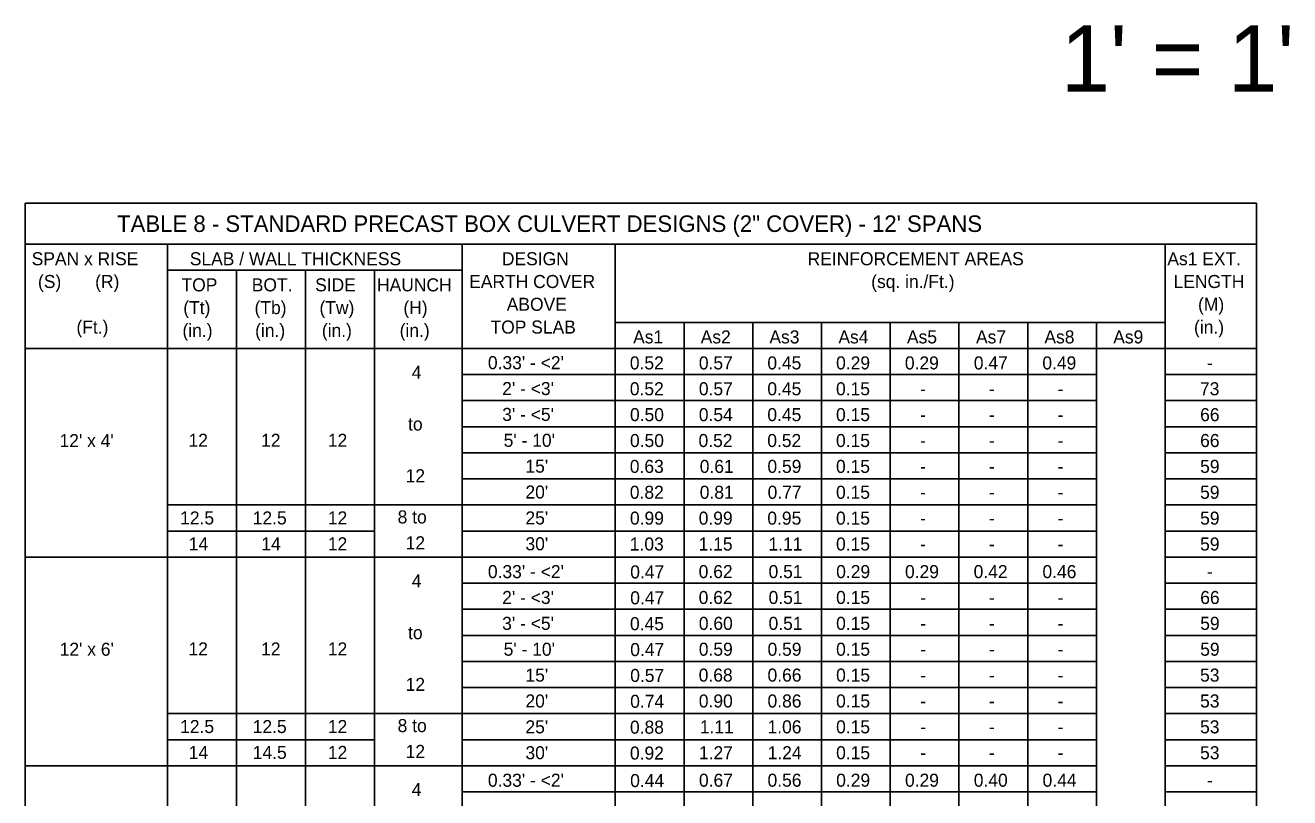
# Model space of a CAD drawing. Extents: x 10351.18 to 10353.4, y 76399.49 to 76400.59.
# Drawn here: x 10351.832 to 10352.443, y 76400.212 to 76400.586 of the extents above; entities that cross this region are included whole.
import ezdxf

# ---------------------------------------------------------------- set-up
doc = ezdxf.new("R2010")
doc.units = 0
doc.layers.add('AdhocPoint_dp', color=7, linetype='Continuous')
doc.layers.add('PlotBorder_dp', color=7, linetype='Continuous')

msp = doc.modelspace()

# ---------------------------------------------------------------- linework, layer by layer
at = {"layer": 'PlotBorder_dp'}
for p, q in [((10351.83244, 76400.49971), (10351.83244, 76399.92549)), ((10351.83244, 76400.49971), (10352.42718, 76400.49971)), ((10352.42718, 76400.49971), (10352.42718, 76399.92549)), ((10351.83244, 76400.47984), (10352.42718, 76400.47984)), ((10351.90108, 76400.47984), (10351.90108, 76399.92549)), ((10352.04352, 76400.47984), (10352.04352, 76399.92549)), ((10352.1174, 76400.47984), (10352.1174, 76399.92549)), ((10352.38299, 76400.47984), (10352.38299, 76399.92549)), ((10351.90108, 76400.46724), (10352.04352, 76400.46724)), ((10351.93444, 76400.46724), (10351.93444, 76399.92549)), ((10351.9678, 76400.46724), (10351.9678, 76399.92549)), ((10352.00116, 76400.46724), (10352.00116, 76399.92549)), ((10352.1174, 76400.44209), (10352.38299, 76400.44209)), ((10352.1506, 76400.44209), (10352.1506, 76399.92549)), ((10352.1838, 76400.44209), (10352.1838, 76399.92549)), ((10352.217, 76400.44209), (10352.217, 76399.92549)), ((10352.2502, 76400.44209), (10352.2502, 76399.92549)), ((10352.28339, 76400.44209), (10352.28339, 76399.92549)), ((10352.28339, 76400.44209), (10352.28339, 76399.92549)), ((10352.31659, 76400.44209), (10352.31659, 76399.92549)), ((10352.34979, 76400.44209), (10352.34979, 76399.92549)), ((10351.83244, 76400.42949), (10352.42718, 76400.42949)), ((10352.04352, 76400.41689), (10352.34979, 76400.41689)), ((10352.38299, 76400.41689), (10352.42718, 76400.41689)), ((10352.04352, 76400.40429), (10352.34979, 76400.40429)), ((10352.38299, 76400.40429), (10352.42718, 76400.40429)), ((10352.04352, 76400.39169), (10352.34979, 76400.39169)), ((10352.38299, 76400.39169), (10352.42718, 76400.39169)), ((10352.04352, 76400.37909), (10352.34979, 76400.37909)), ((10352.38299, 76400.37909), (10352.42718, 76400.37909)), ((10352.04352, 76400.36649), (10352.34979, 76400.36649)), ((10352.38299, 76400.36649), (10352.42718, 76400.36649)), ((10352.04352, 76400.35389), (10351.90108, 76400.35389)), ((10352.04352, 76400.35389), (10352.34979, 76400.35389)), ((10352.38299, 76400.35389), (10352.42718, 76400.35389)), ((10352.00116, 76400.34129), (10351.90108, 76400.34129)), ((10352.04352, 76400.34129), (10352.34979, 76400.34129)), ((10352.38299, 76400.34129), (10352.42718, 76400.34129)), ((10351.83244, 76400.32869), (10352.34979, 76400.32869)), ((10352.04414, 76400.32869), (10352.11631, 76400.32869)), ((10352.38299, 76400.32869), (10352.42718, 76400.32869)), ((10352.04352, 76400.31609), (10352.34979, 76400.31609)), ((10352.38299, 76400.31609), (10352.42718, 76400.31609)), ((10352.04352, 76400.30349), (10352.34979, 76400.30349)), ((10352.38299, 76400.30349), (10352.42718, 76400.30349)), ((10352.04352, 76400.29089), (10352.34979, 76400.29089)), ((10352.38299, 76400.29089), (10352.42718, 76400.29089)), ((10352.04352, 76400.27829), (10352.34979, 76400.27829)), ((10352.38299, 76400.27829), (10352.42718, 76400.27829)), ((10352.04352, 76400.26569), (10352.34979, 76400.26569)), ((10352.38299, 76400.26569), (10352.42718, 76400.26569)), ((10352.04352, 76400.25309), (10351.90108, 76400.25309)), ((10352.04352, 76400.25309), (10352.34979, 76400.25309)), ((10352.38299, 76400.25309), (10352.42718, 76400.25309)), ((10352.00116, 76400.24049), (10351.90108, 76400.24049)), ((10352.04352, 76400.24049), (10352.34979, 76400.24049)), ((10352.04414, 76400.24049), (10352.11631, 76400.24049)), ((10352.38299, 76400.24049), (10352.42718, 76400.24049)), ((10351.83244, 76400.22789), (10352.34979, 76400.22789)), ((10352.38299, 76400.22789), (10352.42718, 76400.22789)), ((10352.04352, 76400.21529), (10352.34979, 76400.21529)), ((10352.38299, 76400.21529), (10352.42718, 76400.21529))]:
    msp.add_line(p, q, dxfattribs=at)

# ---------------------------------------------------------------- texts
at = {"layer": 'AdhocPoint_dp'}
for s, height, p in [("1' = 1'", 0.032, (10352.33259, 76400.55363)), ('TABLE 8 - STANDARD PRECAST BOX CULVERT DESIGNS (2" COVER) - 12\' SPANS', 0.008, (10351.87677, 76400.48578)), ('SLAB / WALL THICKNESS', 0.0063, (10351.9119, 76400.46968)), ('As1', 0.0063, (10352.12602, 76400.43192)), ('As2', 0.0063, (10352.15865, 76400.43192)), ('As3', 0.0063, (10352.19185, 76400.43192)), ('As4', 0.0063, (10352.22517, 76400.43192)), ('As5', 0.0063, (10352.25827, 76400.43192)), ('As7', 0.0063, (10352.29162, 76400.43192)), ('As8', 0.0063, (10352.32466, 76400.43192)), ('As9', 0.0063, (10352.35791, 76400.43192)), ("12' x 4'", 0.0063, (10351.84898, 76400.38182))]:
    msp.add_text(s, height=height, dxfattribs=at).set_placement(p)
at = {"layer": 'PlotBorder_dp'}
for s, p in [('SPAN x RISE', (10351.83553, 76400.46969)), ('DESIGN', (10352.06262, 76400.46969)), ('REINFORCEMENT AREAS', (10352.2103, 76400.46969)), ('(S)       (R)', (10351.83857, 76400.45869)), ('EARTH COVER', (10352.04683, 76400.45869)), ('(sq. in./Ft.)', (10352.241, 76400.45869)), ('TOP', (10351.9079, 76400.45708)), ('BOT.', (10351.94183, 76400.45708)), ('SIDE', (10351.97243, 76400.45708)), ('HAUNCH', (10352.00232, 76400.45708)), ('(Tt)', (10351.90875, 76400.44608)), ('(Tb)', (10351.94317, 76400.44608)), ('(Tw)', (10351.97453, 76400.44608)), ('(H)', (10352.01506, 76400.44608)), ('ABOVE', (10352.06497, 76400.44769)), ('(Ft.)', (10351.85715, 76400.43669)), ('(in.)', (10351.90836, 76400.43508)), ('(in.)', (10351.94345, 76400.43508)), ('(in.)', (10351.97568, 76400.43508)), ('(in.)', (10352.01325, 76400.43508)), ('TOP SLAB', (10352.05714, 76400.43669)), ("0.33' - <2'", (10352.05588, 76400.41948)), ('0.52', (10352.12443, 76400.41937)), ('0.57', (10352.15777, 76400.41937)), ('0.45', (10352.19085, 76400.41937)), ('0.29', (10352.22405, 76400.41937)), ('0.29', (10352.25728, 76400.41937)), ('0.47', (10352.29056, 76400.41937)), ('0.49', (10352.32367, 76400.41937)), ('4', (10352.0191, 76400.41485)), ("2' - <3'", (10352.06278, 76400.40698)), ('0.52', (10352.12443, 76400.40687)), ('0.57', (10352.15777, 76400.40687)), ('0.45', (10352.19085, 76400.40687)), ('0.15', (10352.22401, 76400.40687)), ('-', (10352.26462, 76400.40687)), ('-', (10352.29782, 76400.40687)), ('-', (10352.33101, 76400.40687)), ("3' - <5'", (10352.06278, 76400.39448)), ('0.50', (10352.1245, 76400.39437)), ('0.54', (10352.15775, 76400.39437)), ('0.45', (10352.19085, 76400.39437)), ('0.15', (10352.22401, 76400.39437)), ('-', (10352.26462, 76400.39437)), ('-', (10352.29782, 76400.39437)), ('-', (10352.33101, 76400.39437)), ('to', (10352.01732, 76400.38985)), ('12', (10351.91127, 76400.38198)), ('12', (10351.94634, 76400.38198)), ('12', (10351.97858, 76400.38198)), ("5' - 10'", (10352.06349, 76400.38198)), ('0.50', (10352.1245, 76400.38187)), ('0.52', (10352.15762, 76400.38187)), ('0.52', (10352.19082, 76400.38187)), ('0.15', (10352.22401, 76400.38187)), ('-', (10352.26462, 76400.38187)), ('-', (10352.29782, 76400.38187)), ('-', (10352.33101, 76400.38187)), ("15'", (10352.07401, 76400.36948)), ('0.63', (10352.12442, 76400.36937)), ('0.61', (10352.15819, 76400.36937)), ('0.59', (10352.19089, 76400.36937)), ('0.15', (10352.22401, 76400.36937)), ('12', (10352.01615, 76400.36485)), ('-', (10352.26462, 76400.36937)), ('-', (10352.29782, 76400.36937)), ('-', (10352.33101, 76400.36937)), ("20'", (10352.07401, 76400.35698)), ('0.82', (10352.12443, 76400.35687)), ('0.81', (10352.15819, 76400.35687)), ('0.77', (10352.19097, 76400.35687)), ('0.15', (10352.22401, 76400.35687)), ('-', (10352.26462, 76400.35687)), ('-', (10352.29782, 76400.35687)), ('-', (10352.33101, 76400.35687)), ('12.5', (10351.90723, 76400.34448)), ('12.5', (10351.9423, 76400.34448)), ('12', (10351.97858, 76400.34448)), ('8 to', (10352.01228, 76400.34496)), ("25'", (10352.07401, 76400.34448)), ('0.99', (10352.12449, 76400.34437)), ('0.99', (10352.15769, 76400.34437)), ('0.95', (10352.19085, 76400.34437)), ('0.15', (10352.22401, 76400.34437)), ('-', (10352.26462, 76400.34437)), ('-', (10352.29782, 76400.34437)), ('-', (10352.33101, 76400.34437)), ('14', (10351.9114, 76400.33198)), ('14', (10351.94646, 76400.33198)), ('12', (10351.97858, 76400.33198)), ('12', (10352.01615, 76400.33246)), ("30'", (10352.07401, 76400.33198)), ('1.03', (10352.12442, 76400.33187)), ('1.15', (10352.15765, 76400.33187)), ('1.11', (10352.19139, 76400.33187)), ('0.15', (10352.22401, 76400.33187)), ('-', (10352.26462, 76400.33187)), ('-', (10352.29782, 76400.33187)), ('-', (10352.33101, 76400.33187)), ("0.33' - <2'", (10352.05588, 76400.31854)), ('0.47', (10352.12462, 76400.31838)), ('0.62', (10352.15768, 76400.31854)), ('0.51', (10352.19144, 76400.31854)), ('0.29', (10352.2241, 76400.31854)), ('0.29', (10352.25733, 76400.31854)), ('0.42', (10352.29048, 76400.31854)), ('0.46', (10352.32372, 76400.31854)), ('4', (10352.0191, 76400.31405)), ('-', (10352.40319, 76400.31854)), ("2' - <3'", (10352.06278, 76400.30604)), ('0.47', (10352.12462, 76400.30588)), ('0.62', (10352.15768, 76400.30604)), ('0.51', (10352.19144, 76400.30604)), ('0.15', (10352.22406, 76400.30604)), ('66', (10352.39992, 76400.30604)), ('-', (10352.26467, 76400.30604)), ('-', (10352.29788, 76400.30604)), ('-', (10352.33106, 76400.30604)), ("3' - <5'", (10352.06278, 76400.29354)), ('0.45', (10352.1245, 76400.29338)), ('0.60', (10352.15775, 76400.29354)), ('0.51', (10352.19144, 76400.29354)), ('0.15', (10352.22406, 76400.29354)), ('59', (10352.39992, 76400.29354)), ('to', (10352.01732, 76400.28905)), ('-', (10352.26467, 76400.29354)), ('-', (10352.29788, 76400.29354)), ('-', (10352.33106, 76400.29354)), ("12' x 6'", (10351.84905, 76400.28104)), ('12', (10351.91127, 76400.28118)), ('12', (10351.94634, 76400.28118)), ('12', (10351.97858, 76400.28118)), ("5' - 10'", (10352.06349, 76400.28104)), ('0.47', (10352.12462, 76400.28088)), ('0.59', (10352.15774, 76400.28104)), ('0.59', (10352.19094, 76400.28104)), ('0.15', (10352.22406, 76400.28104)), ('59', (10352.39992, 76400.28104)), ('-', (10352.26467, 76400.28104)), ('-', (10352.29788, 76400.28104)), ('-', (10352.33106, 76400.28104)), ('12', (10352.01615, 76400.26405)), ("15'", (10352.07401, 76400.26854)), ('0.57', (10352.12462, 76400.26838)), ('0.68', (10352.15769, 76400.26854)), ('0.66', (10352.19094, 76400.26854)), ('0.15', (10352.22406, 76400.26854)), ('-', (10352.26467, 76400.26854)), ('-', (10352.29788, 76400.26854)), ('-', (10352.33106, 76400.26854)), ('53', (10352.39985, 76400.26854)), ("20'", (10352.07401, 76400.25604)), ('0.74', (10352.1246, 76400.25588)), ('0.90', (10352.15775, 76400.25604)), ('0.86', (10352.19094, 76400.25604)), ('0.15', (10352.22406, 76400.25604)), ('-', (10352.26467, 76400.25604)), ('-', (10352.29788, 76400.25604)), ('-', (10352.33106, 76400.25604)), ('53', (10352.39985, 76400.25604)), ('8 to', (10352.01228, 76400.24416)), ('12.5', (10351.90723, 76400.24368)), ('12.5', (10351.9423, 76400.24368)), ('12', (10351.97858, 76400.24368)), ("25'", (10352.07401, 76400.24354)), ('0.88', (10352.1245, 76400.24338)), ('1.11', (10352.15824, 76400.24354)), ('1.06', (10352.19094, 76400.24354)), ('0.15', (10352.22406, 76400.24354)), ('-', (10352.26467, 76400.24354)), ('-', (10352.29788, 76400.24354)), ('-', (10352.33106, 76400.24354)), ('53', (10352.39985, 76400.24354)), ('14', (10351.9114, 76400.23118)), ('14.5', (10351.9423, 76400.23118)), ('12', (10351.97858, 76400.23118)), ('12', (10352.01615, 76400.23166)), ("30'", (10352.07401, 76400.23104)), ('0.92', (10352.12448, 76400.23088)), ('1.27', (10352.15782, 76400.23104)), ('1.24', (10352.191, 76400.23104)), ('0.15', (10352.22406, 76400.23104)), ('-', (10352.26467, 76400.23104)), ('-', (10352.29788, 76400.23104)), ('-', (10352.33106, 76400.23104)), ('53', (10352.39985, 76400.23104)), ("0.33' - <2'", (10352.05588, 76400.21776)), ('0.44', (10352.1246, 76400.2176)), ('0.67', (10352.15782, 76400.21776)), ('0.56', (10352.19094, 76400.21776)), ('0.29', (10352.2241, 76400.21776)), ('0.29', (10352.25733, 76400.21776)), ('0.40', (10352.29055, 76400.21776)), ('0.44', (10352.32378, 76400.21776)), ('-', (10352.40319, 76400.21776)), ('4', (10352.0191, 76400.21325))]:
    msp.add_text(s, height=0.0063, dxfattribs=at).set_placement(p)
for s, p in [('As1 EXT.', (10352.38404, 76400.46969)), ('LENGTH', (10352.38706, 76400.45869)), ('(M)', (10352.39887, 76400.44769)), ('(in.)', (10352.39691, 76400.43669)), ('-', (10352.40313, 76400.41937)), ('73', (10352.3998, 76400.40687)), ('66', (10352.39987, 76400.39437)), ('66', (10352.39987, 76400.38187)), ('59', (10352.39987, 76400.36937)), ('59', (10352.39987, 76400.35687)), ('59', (10352.39987, 76400.34437)), ('59', (10352.39987, 76400.33187))]:
    msp.add_text(s, height=0.0063, rotation=360, dxfattribs=at).set_placement(p)

doc.saveas('drawing.dxf')
